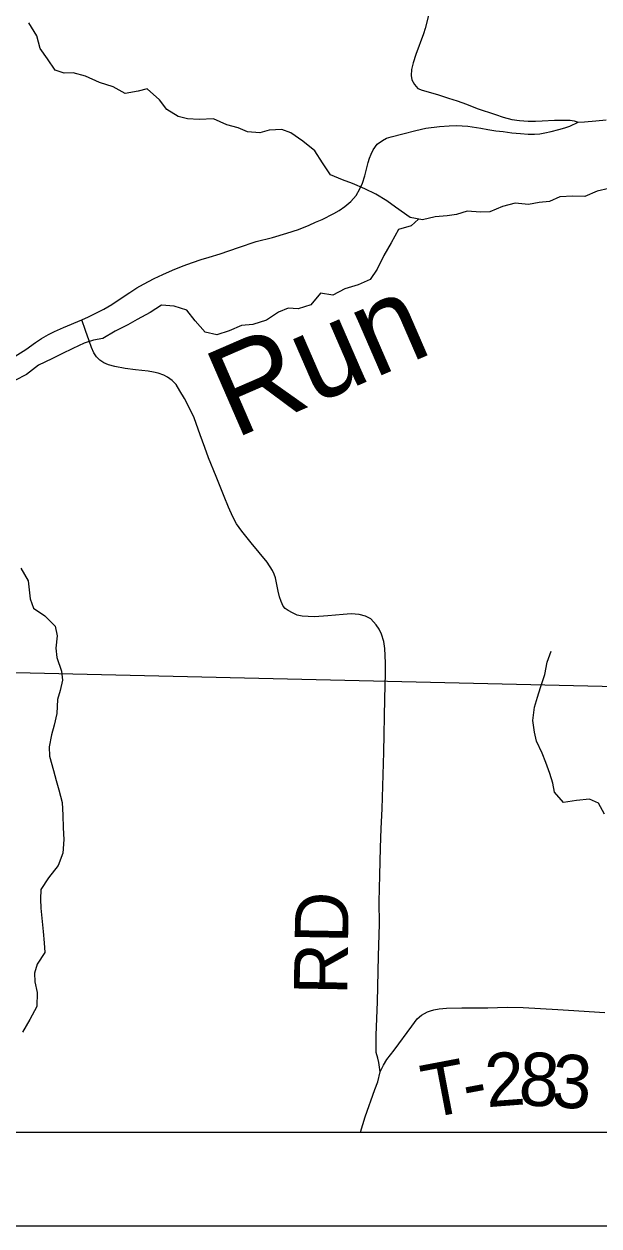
# Model space of a CAD drawing. Extents: x 0 to 34, y 0 to 22.
# Drawn here: x 4.695 to 5.307, y 14 to 15.28 of the extents above; entities that cross this region are included whole.
import ezdxf

# ---------------------------------------------------------------- set-up
doc = ezdxf.new("R2010")
doc.units = 0
for name, color, linetype in [('GM_X_Corporation', 7, 'Continuous'), ('GM_X_County_Road', 7, 'Continuous'), ('GM_X_Minor_River', 7, 'Continuous'), ('GM_X_Minor_River_Text', 7, 'Continuous'), ('GM_X_Township_Road', 7, 'Continuous'), ('GM_X_Township_Road_Text', 7, 'Continuous'), ('SH_Data', 7, 'Continuous')]:
    doc.layers.add(name, color=color, linetype=linetype)

msp = doc.modelspace()

# ---------------------------------------------------------------- linework, layer by layer
at = {"layer": 'GM_X_Corporation'}
for points in [[(4.3545, 15.5959), (4.3388, 15.081), (4.3354, 14.967), (4.3352, 14.9629), (4.3241, 14.5964), (4.324, 14.5949), (4.3124, 14.1), (8.9, 14.1)], [(2.1, 14.1), (8.9, 14.1)]]:
    msp.add_lwpolyline(points, dxfattribs=at)
msp.add_lwpolyline([(4.3084, 14.1), (5.3175, 14.1), (5.3249, 14.5126), (5.3254, 14.5744), (4.3202, 14.5977)], close=True, dxfattribs=at)
at = {"layer": 'GM_X_County_Road'}
msp.add_lwpolyline([(4.6823, 14.9246), (4.6965, 14.9335), (4.7071, 14.9409), (4.7133, 14.9451), (4.7207, 14.9495), (4.727, 14.9527), (4.7367, 14.9571), (4.7563, 14.965), (4.7634, 14.9684), (4.7713, 14.9722), (4.7796, 14.9765), (4.7881, 14.9816), (4.7961, 14.9869), (4.8074, 14.9943), (4.8149, 14.9991), (4.8218, 15.0031), (4.8332, 15.0091), (4.8426, 15.0135), (4.8527, 15.0181), (4.8641, 15.0227), (4.8739, 15.0263), (4.8833, 15.0293), (4.8916, 15.0318), (4.9036, 15.0356), (4.923, 15.0422), (4.9418, 15.0484), (4.9591, 15.053), (4.9746, 15.0573), (4.9869, 15.0614), (4.9983, 15.066), (5.005, 15.069), (5.0119, 15.072), (5.0245, 15.0783), (5.03, 15.0816), (5.0362, 15.0857), (5.0426, 15.0911), (5.0484, 15.0976), (5.0523, 15.1046), (5.0549, 15.1108), (5.0576, 15.1186), (5.0609, 15.1327), (5.0624, 15.1373), (5.0641, 15.1415), (5.0663, 15.1463), (5.0706, 15.1522), (5.0761, 15.1562), (5.0806, 15.1585), (5.0856, 15.1602), (5.0978, 15.1633), (5.1116, 15.1669), (5.1225, 15.1692), (5.1369, 15.1711), (5.1472, 15.1719), (5.1549, 15.172), (5.161, 15.1718), (5.1672, 15.1714), (5.1809, 15.1691), (5.1883, 15.1678), (5.197, 15.1665), (5.2047, 15.1656), (5.214, 15.1644), (5.2233, 15.1636), (5.2312, 15.1629), (5.2382, 15.1629), (5.2438, 15.1634), (5.2491, 15.1644), (5.2557, 15.1658), (5.2638, 15.1678), (5.2702, 15.1696), (5.2755, 15.1713), (5.2846, 15.1755), (5.2914, 15.1759), (5.3034, 15.1771), (5.3143, 15.1781)], dxfattribs=at)
at = {"layer": 'GM_X_Minor_River'}
for points in [[(5.2651, 15.096), (5.2541, 15.091), (5.2431, 15.0902), (5.2318, 15.0879), (5.2174, 15.0894), (5.2038, 15.0859), (5.1906, 15.0802), (5.1807, 15.0798), (5.1663, 15.0809), (5.155, 15.0774), (5.1451, 15.0759), (5.1323, 15.0747), (5.119, 15.0716), (5.1058, 15.0742), (5.0902, 15.0851), (5.0807, 15.0919), (5.0693, 15.0991), (5.0576, 15.1048), (5.0443, 15.1104), (5.0337, 15.1142), (5.0208, 15.1194), (5.0124, 15.1323), (5.0044, 15.1451), (4.9915, 15.1553), (4.9786, 15.1644), (4.9692, 15.1678), (4.9555, 15.1673), (4.9457, 15.1643), (4.9324, 15.1654), (4.9226, 15.1695), (4.9105, 15.1729), (4.8964, 15.1793), (4.8813, 15.1785), (4.8688, 15.1792), (4.8589, 15.1818), (4.8468, 15.1893), (4.8388, 15.1996), (4.8259, 15.2113), (4.8161, 15.2086), (4.8025, 15.2063), (4.7896, 15.2134), (4.7752, 15.2179), (4.76, 15.2247), (4.7471, 15.2281), (4.7373, 15.228), (4.7278, 15.231), (4.7198, 15.2431), (4.7118, 15.2541), (4.7084, 15.2677), (4.7, 15.2813)], [(5.3173, 15.1049), (5.3048, 15.1022), (5.2916, 15.0965), (5.2787, 15.0968), (5.2651, 15.096)], [(5.1147, 15.0724), (5.1069, 15.0651), (5.0933, 15.0613), (5.0854, 15.0472), (5.0775, 15.0335), (5.0707, 15.0191), (5.0632, 15.0081), (5.0503, 15.0024), (5.0363, 14.9981), (5.0235, 14.9913), (5.0102, 14.9935), (5, 14.981), (4.9864, 14.9767), (4.9758, 14.9775), (4.9656, 14.9733), (4.9527, 14.9649), (4.9384, 14.9603), (4.9263, 14.9591), (4.913, 14.9534), (4.8998, 14.9491), (4.8876, 14.9521), (4.877, 14.9642), (4.8679, 14.9756), (4.8546, 14.9797), (4.841, 14.9808), (4.8289, 14.9728), (4.8153, 14.9655), (4.8051, 14.9598), (4.7919, 14.953), (4.7786, 14.9453), (4.7688, 14.9434), (4.7586, 14.9403), (4.7465, 14.9346), (4.7348, 14.9289), (4.7242, 14.9235), (4.7102, 14.917), (4.6973, 14.9068), (4.6849, 14.9006)], [(4.6915, 14.7008), (4.6991, 14.6872), (4.7003, 14.6774), (4.7011, 14.6679), (4.7049, 14.658), (4.717, 14.6497), (4.728, 14.6388), (4.73, 14.6286), (4.7285, 14.6153), (4.7297, 14.6054), (4.7346, 14.591), (4.7358, 14.5812), (4.7332, 14.5702), (4.7302, 14.5607), (4.7295, 14.5459), (4.7269, 14.5334), (4.7239, 14.5231), (4.7216, 14.5102), (4.722, 14.5004), (4.7262, 14.4852), (4.7289, 14.4746), (4.7316, 14.4647), (4.7354, 14.4511), (4.7362, 14.4374), (4.7363, 14.4242), (4.7371, 14.4117), (4.736, 14.3969), (4.7311, 14.384), (4.7209, 14.3707), (4.7126, 14.3585), (4.7123, 14.3479), (4.7127, 14.3384), (4.7139, 14.3244), (4.715, 14.3137), (4.7162, 14.3016), (4.717, 14.2914), (4.7087, 14.2788), (4.7057, 14.2693), (4.7061, 14.2599), (4.7088, 14.2485), (4.7085, 14.2337), (4.7009, 14.22), (4.693, 14.2063)], [(5.3125, 14.4386), (5.306, 14.4504), (5.2966, 14.4545), (5.2829, 14.453), (5.2689, 14.451), (5.2594, 14.462), (5.2575, 14.4718), (5.2544, 14.4821), (5.2502, 14.4938), (5.2461, 14.5036), (5.2403, 14.5165), (5.238, 14.526), (5.2361, 14.5385), (5.238, 14.5525), (5.2413, 14.5632), (5.2443, 14.5734), (5.2492, 14.5875), (5.2514, 14.6004), (5.2559, 14.6121)]]:
    msp.add_lwpolyline(points, dxfattribs=at)
at = {"layer": 'GM_X_Township_Road'}
for points in [[(5.126, 15.2921), (5.1216, 15.2756), (5.1199, 15.2699), (5.1118, 15.2479), (5.109, 15.239), (5.107, 15.2318), (5.1068, 15.2252), (5.1076, 15.2206), (5.1104, 15.2157), (5.114, 15.2117), (5.1185, 15.2097), (5.1349, 15.2051), (5.1464, 15.2014), (5.1557, 15.1984), (5.1656, 15.1947), (5.177, 15.1903), (5.1965, 15.1837), (5.2045, 15.1811), (5.2139, 15.1785), (5.2222, 15.1775), (5.2312, 15.1769), (5.239, 15.1769), (5.2463, 15.1772), (5.2592, 15.1779), (5.276, 15.1778), (5.2801, 15.177), (5.2846, 15.1755)], [(5.0529, 14.1), (5.0577, 14.1164), (5.0682, 14.1453), (5.0713, 14.1536), (5.0739, 14.1641), (5.0722, 14.174), (5.0713, 14.1787), (5.0696, 14.1849), (5.0695, 14.1921), (5.0696, 14.2031), (5.0711, 14.2388), (5.072, 14.2875), (5.0729, 14.3217), (5.0727, 14.3452), (5.0734, 14.3736), (5.0743, 14.4026), (5.0748, 14.4235), (5.0758, 14.4442), (5.0777, 14.5046), (5.0786, 14.5613), (5.0793, 14.5889), (5.0793, 14.5999), (5.0788, 14.6151), (5.0776, 14.6226), (5.0752, 14.6302), (5.0727, 14.6355), (5.0696, 14.6403), (5.0637, 14.6466), (5.0581, 14.6495), (5.0513, 14.6512), (5.0428, 14.6519), (5.0345, 14.6514), (5.018, 14.6499), (5.004, 14.6487), (4.997, 14.649), (4.9908, 14.6496), (4.9855, 14.6507), (4.9804, 14.6529), (4.9758, 14.6554), (4.9726, 14.6577), (4.9704, 14.6603), (4.9684, 14.665), (4.9668, 14.6701), (4.9653, 14.6763), (4.9622, 14.6904), (4.9608, 14.6944), (4.9593, 14.6983), (4.9534, 14.7071), (4.945, 14.7172), (4.9364, 14.7276), (4.9266, 14.7401), (4.921, 14.7478), (4.9169, 14.7552), (4.9122, 14.7656), (4.9077, 14.7771), (4.8992, 14.7982), (4.8912, 14.8182), (4.8872, 14.8291), (4.8823, 14.8428), (4.8758, 14.8608), (4.8713, 14.8704), (4.8655, 14.8813), (4.8607, 14.8895), (4.8566, 14.8961), (4.8524, 14.9004), (4.8475, 14.9041), (4.8435, 14.9063), (4.8375, 14.9083), (4.8327, 14.9095), (4.827, 14.9104), (4.8135, 14.9118), (4.8023, 14.9132), (4.7915, 14.9154), (4.7848, 14.9173), (4.7795, 14.9194), (4.7754, 14.9223), (4.7718, 14.9257), (4.769, 14.93), (4.7666, 14.9355), (4.7639, 14.9429), (4.7602, 14.9537), (4.7563, 14.965)], [(5.0739, 14.1641), (5.0772, 14.1712), (5.0807, 14.1773), (5.0886, 14.1872), (5.1075, 14.2127), (5.1132, 14.2206), (5.1176, 14.2244), (5.1242, 14.228), (5.1274, 14.2292), (5.1309, 14.2301), (5.1366, 14.2312), (5.1443, 14.2318), (5.1608, 14.2323), (5.1882, 14.2323), (5.209, 14.2332), (5.2259, 14.2328), (5.2629, 14.2307), (5.2741, 14.2299), (5.3128, 14.2272)]]:
    msp.add_lwpolyline(points, dxfattribs=at)
at = {"layer": 'SH_Data'}
for p, q in [((2.1, 14.1), (8.9, 14.1)), ((2, 14), (9, 14))]:
    msp.add_line(p, q, dxfattribs=at)

# ---------------------------------------------------------------- texts
at = {"layer": 'GM_X_Minor_River_Text'}
msp.add_text('Run', height=0.09469, rotation=23.4688, dxfattribs=at).set_placement((4.9187, 14.8381))
at = {"layer": 'GM_X_Township_Road_Text'}
for s, height, rotation, p in [('RD', 0.05682, 89.0128, (5.0386, 14.2458)), ('2', 0.0568, 4.4227, (5.1874, 14.1264)), ('8', 0.0568, 356.4227, (5.2202, 14.1291)), ('T', 0.0568, 10.751, (5.1243, 14.1144)), ('3', 0.0568, 356.2295, (5.255, 14.1269)), ('-', 0.0568, 10.6225, (5.166, 14.1223))]:
    msp.add_text(s, height=height, rotation=rotation, dxfattribs=at).set_placement(p)

doc.saveas('drawing.dxf')
